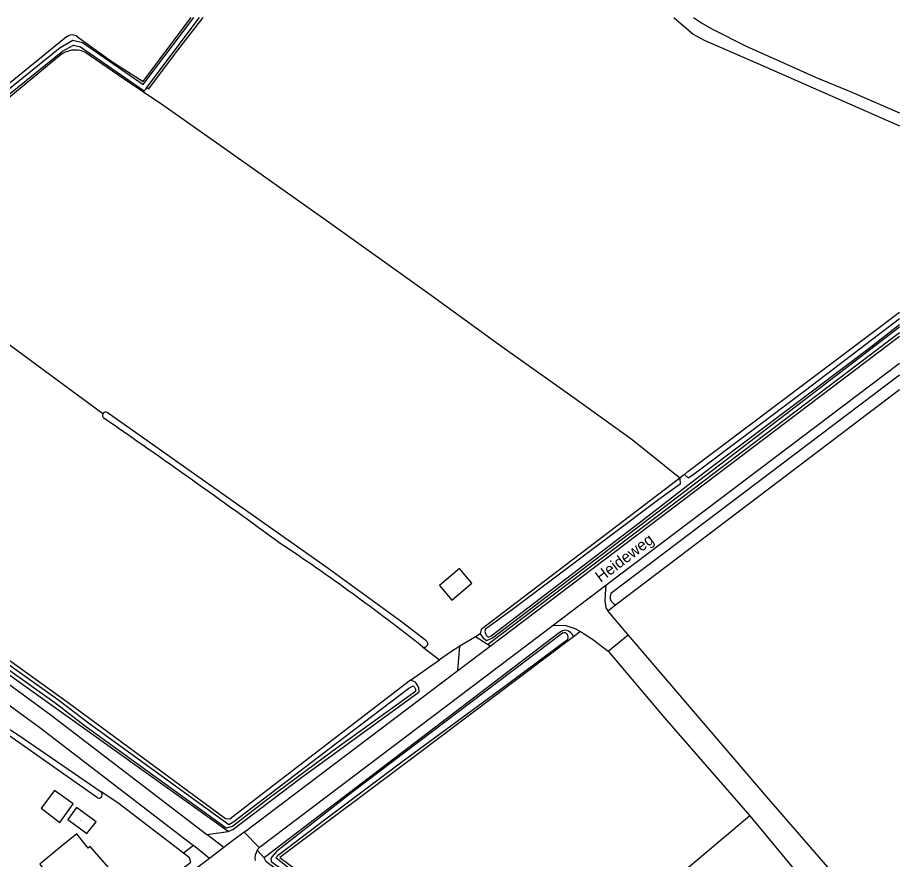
# Model space of a CAD drawing. Extents: x 141000 to 143000, y 400580 to 403500.
# Drawn here: x 142807.3 to 143000, y 403316 to 403500 of the extents above; entities that cross this region are included whole.
import ezdxf

# ---------------------------------------------------------------- set-up
doc = ezdxf.new("R2010")
doc.units = 0
for name, color, linetype in [('gg-afsc-muur', 7, 'Continuous'), ('gg-anno-openbare ruimte label', 7, 'Continuous'), ('gg-bbg-overig bouwwerk', 7, 'Continuous'), ('gg-knt-bronhoudergrens', 7, 'Continuous'), ('gg-knt-onverhard', 7, 'Continuous'), ('gg-knt-verharding', 7, 'Continuous'), ('gg-kntw-bovenkant insteek waterloop', 7, 'Continuous'), ('gg-kntw-waterlijn', 7, 'Continuous'), ('gt-grn-vlakafsluiter', 7, 'Continuous'), ('gt-grn-weggrens', 7, 'Continuous'), ('gx-grn-maaiveld', 7, 'Continuous'), ('kenmerkpunt-x pandkandidaat', 7, 'Continuous')]:
    doc.layers.add(name, color=color, linetype=linetype)

msp = doc.modelspace()

# ---------------------------------------------------------------- linework, layer by layer
at = {"layer": 'gg-afsc-muur'}
for points in [[(143000, 403257.58), (142974.61, 403289.01), (142983.17, 403296.46), (142992.55, 403304.89), (142971.44, 403329.16), (142940.76, 403365.11)], [(142967.32, 403325.5), (142947.35, 403308.65), (142956.55, 403298.23), (142927.33, 403272.64)]]:
    msp.add_lwpolyline(points, dxfattribs=at)
at = {"layer": 'gg-bbg-overig bouwwerk'}
for points in [[(142906.56, 403376.36), (142903.86, 403379.58), (142899.47, 403375.9), (142902.18, 403372.68), (142906.56, 403376.36)], [(142819.4, 403328.13), (142815.33, 403331.03), (142812.43, 403327.18), (142816.5, 403324.06), (142819.4, 403328.13)]]:
    msp.add_lwpolyline(points, dxfattribs=at)
at = {"layer": 'gg-knt-bronhoudergrens'}
for p, q in [((142825.88, 403413.4), (142772.65, 403452.66)), ((142893.17, 403355.15), (142899.51, 403359.63))]:
    msp.add_line(p, q, dxfattribs=at)
msp.add_lwpolyline([(142967.32, 403325.5), (142947.35, 403308.65), (142956.55, 403298.23), (142927.33, 403272.64)], dxfattribs=at)
at = {"layer": 'gg-knt-onverhard'}
msp.add_line((142895.76, 403362.49), (142899.51, 403359.63), dxfattribs=at)
at = {"layer": 'gg-knt-verharding'}
for p, q in [((142860.04, 403318.57), (142924.33, 403367.21)), ((142903.47, 403357.29), (142910.53, 403362.63)), ((142903.47, 403357.29), (142903.95, 403362.58)), ((142856.76, 403321.94), (142903.47, 403357.29)), ((142852.34, 403318.59), (142848.6, 403321.46)), ((142860.04, 403318.57), (142856.76, 403321.94)), ((142849.23, 403316.22), (142845.71, 403319.06))]:
    msp.add_line(p, q, dxfattribs=at)
for points in [[(142595.45, 403500), (142629.17, 403476.1), (142673.83, 403443.54), (142712.26, 403416.36), (142765.07, 403379.18), (142812.16, 403344.83), (142845.71, 403319.06)], [(142604.52, 403500), (142632.22, 403479.92), (142678.54, 403445.48), (142714.62, 403419.55), (142767.02, 403382.42), (142814.6, 403347.5), (142848.6, 403321.46)], [(142856.76, 403321.94), (142854.22, 403320.02), (142852.34, 403318.59)], [(142849.23, 403316.22), (142846.27, 403313.98), (142821.92, 403295.58)]]:
    msp.add_lwpolyline(points, dxfattribs=at)
for centre, radius, start, end in [((142862.86, 403316.16), 3.71, 150.6856, 185.8925), ((142862.83, 403316.19), 3.66, 139.4869, 150.8529)]:
    msp.add_arc(centre, radius, start, end, dxfattribs=at)
at = {"layer": 'gg-kntw-bovenkant insteek waterloop'}
msp.add_line((142824.75, 403329.45), (142800.19, 403346.65), dxfattribs=at)
for points in [[(142893.17, 403355.15), (142861.1, 403330.58), (142853.67, 403324.76), (142852.71, 403324.86), (142818.65, 403349.97), (142769.65, 403385.22), (142725.71, 403417.52)], [(142853.32, 403322.06), (142767.49, 403383.4), (142722.71, 403416.24)], [(142896.51, 403363.84), (142891.16, 403367.91), (142875.15, 403379.56), (142856.35, 403392.88), (142826.85, 403413.68)], [(142928.77, 403364.68), (142928.54, 403365.14), (142928.21, 403365.53), (142927.71, 403365.87), (142927.29, 403366.03), (142926.85, 403366.1), (142926.34, 403365.97), (142925.65, 403365.53), (142861.14, 403316.35)], [(142928.77, 403364.68), (142894.25, 403338.61), (142864.62, 403316.43), (142875.2, 403308.55), (142895.15, 403294.49), (142914.48, 403280.19)], [(142853.32, 403322.06), (142854.3, 403322.54), (142868.81, 403333.54), (142895.01, 403352.65), (142894.97, 403353.56), (142894.24, 403354.72), (142893.17, 403355.15)], [(142800.91, 403347.31), (142807.38, 403343.19), (142825.51, 403330.74)], [(142914.48, 403280.19), (142914.74, 403278.85), (142914.01, 403278.26), (142913.43, 403278.56), (142882.1, 403300.7), (142861.63, 403315.49), (142861.14, 403316.35)]]:
    msp.add_lwpolyline(points, dxfattribs=at)
for centre, radius, start, end in [((142826.51, 403413.05), 0.715, 151.044, 239.6172), ((142826.51, 403413.05), 0.715, 60.9592, 151.2266), ((141738.31, 401839.77), 1912.24, 53.91216, 55.32796), ((142604.25, 402993.89), 469.94, 51.6602, 56.3473), ((142896.16, 403363.15), 0.772, 305.4627, 63.0485), ((142896.16, 403363.15), 0.773, 239.1139, 305.3643), ((142825.05, 403330.13), 0.753, 245.7892, 53.1632)]:
    msp.add_arc(centre, radius, start, end, dxfattribs=at)
at = {"layer": 'gg-kntw-waterlijn'}
msp.add_line((142835.53, 403484.71), (142847.01, 403500), dxfattribs=at)
for points in [[(142780.76, 403376.1), (142810.98, 403354.58), (142816.01, 403351.02), (142822.75, 403345.86), (142853.42, 403323.63), (142854.52, 403324.27), (142876.78, 403341.25), (142892.79, 403353.4), (142893.72, 403353.93), (142894, 403353.63), (142894.21, 403353.21), (142894.23, 403352.73), (142876.35, 403339.82), (142861.95, 403329.13), (142854.21, 403323.18), (142852.84, 403322.82), (142822.15, 403345.06), (142815.41, 403350.21), (142810.4, 403353.77), (142780.18, 403375.29)], [(142926.37, 403365.48), (142909.35, 403352.56), (142880.64, 403330.85), (142863.85, 403317.73), (142862.92, 403316.61), (142862.64, 403316.21), (142862.67, 403315.57), (142870.65, 403309.82), (142891.9, 403294.45), (142913.15, 403279.4)], [(142913.15, 403279.4), (142913.57, 403279.37), (142913.86, 403279.61), (142913.84, 403280.14), (142910.8, 403282.15), (142871.59, 403310.16), (142864.44, 403315.75), (142863.75, 403316.34), (142864.27, 403317), (142874.63, 403324.86), (142891.52, 403337.54), (142913.77, 403353.88), (142925.24, 403362.38), (142927.45, 403364.06)]]:
    msp.add_lwpolyline(points, dxfattribs=at)
msp.add_arc((142926.69, 403364.6), 0.932, 324.4911, 110.0852, dxfattribs=at)
at = {"layer": 'gt-grn-vlakafsluiter'}
for p, q in [((142848.6, 403321.46), (142853.32, 403322.06)), ((142845.71, 403319.06), (142843.54, 403317.32)), ((142859.63, 403317.98), (142861.14, 403316.35))]:
    msp.add_line(p, q, dxfattribs=at)
for points in [[(142843.54, 403317.32), (142829.19, 403328.33), (142825.51, 403330.74)], [(142820.51, 403296.45), (142845.14, 403315.42), (142844.86, 403316.31), (142843.54, 403317.32)]]:
    msp.add_lwpolyline(points, dxfattribs=at)
at = {"layer": 'gt-grn-weggrens'}
msp.add_line((142852.34, 403318.59), (142849.23, 403316.22), dxfattribs=at)
at = {"layer": 'gx-grn-maaiveld'}
for p, q in [((142834.97, 403483.98), (142834.81, 403483.71)), ((142953.78, 403400.76), (143000, 403435.58)), ((142910.53, 403362.63), (143000, 403430.35)), ((142935.87, 403375.94), (143000, 403424.45)), ((142937.98, 403371.65), (143000, 403418.7)), ((142953.04, 403400.15), (142953.78, 403400.76)), ((142924.33, 403367.21), (142935.87, 403375.94)), ((142940.76, 403365.11), (142936.28, 403370.36)), ((142908.36, 403365.29), (142907.33, 403364.66)), ((142930.29, 403365.84), (142928.77, 403364.68)), ((142907.33, 403364.66), (142903.95, 403362.58)), ((142909.95, 403363), (142907.33, 403364.66)), ((142936.32, 403361.54), (142940.76, 403365.11)), ((142910.53, 403362.63), (142909.95, 403363)), ((142967.32, 403325.5), (142987.9, 403300.71))]:
    msp.add_line(p, q, dxfattribs=at)
for points in [[(142771.14, 403456.86), (142796.03, 403476.86), (142804.74, 403483.96), (142816.56, 403493.5), (142819.32, 403495.07), (142821.46, 403494.55), (142834.75, 403485.35), (142845.76, 403500)], [(142820.4, 403495.83), (142827.88, 403490.39), (142834.71, 403486.01), (142843.64, 403497.92), (142845.19, 403500)], [(142835.53, 403484.71), (142835.96, 403484.42), (142841.79, 403492.2), (142847.82, 403500)], [(142950.73, 403500), (142954.95, 403496.35), (142957.35, 403495.09), (142970.21, 403489.43), (143000, 403476.36)], [(142955.04, 403500), (142956.94, 403498.73), (142959.14, 403497.47), (142966.49, 403493.78), (142974.66, 403490.14), (142981.85, 403486.9), (142989.62, 403483.73), (143000, 403479.21)], [(142817.96, 403495.77), (142801.22, 403482.19), (142787.12, 403470.53), (142777.67, 403462.76), (142770.83, 403457.25)], [(142771.77, 403456.08), (142796.66, 403476.08), (142805.37, 403483.19), (142817.12, 403492.67), (142819.47, 403494), (142821.05, 403493.62), (142834.97, 403483.98)], [(142834.81, 403483.71), (142831.73, 403485.76), (142821.95, 403492.48)], [(142816.44, 403491.63), (142805.69, 403482.78), (142802.98, 403480.49), (142788.01, 403468.39), (142772.08, 403455.69)], [(142834.97, 403483.98), (142835.28, 403484.38), (142835.53, 403484.71)], [(142952.02, 403399.32), (142941.57, 403407.68), (142928.62, 403417.05), (142913.09, 403428.06), (142897.16, 403439.61), (142874.68, 403455.67), (142852.05, 403471.69), (142839.01, 403480.83), (142834.81, 403483.71)], [(142952.02, 403399.32), (142952.06, 403398.03), (142947.42, 403394.67), (142915.42, 403370.62), (142909.54, 403366.3), (142909.4, 403365.82), (142909.69, 403365.03), (142910.12, 403364.59), (142910.78, 403364.83), (142943.42, 403389.82), (142958.26, 403401.31), (142993.37, 403427.77), (143000, 403432.9)], [(142953.04, 403400.15), (142953.82, 403399.37), (142954.86, 403400.07), (142979.52, 403418.58), (143000, 403434.23)], [(142908.36, 403365.29), (142909.06, 403364.39), (142909.84, 403363.86), (142911.07, 403364.44), (142961.95, 403403.17), (143000, 403432.39)], [(142909.95, 403363), (142952.44, 403395.1), (143000, 403431.15)], [(143000, 403421.84), (142936.93, 403374.12), (142936.77, 403373.47), (142936.79, 403372.85), (142937.11, 403372.35), (142937.54, 403371.9), (142937.98, 403371.65)], [(142953.04, 403400.15), (142952.47, 403399.69), (142952.02, 403399.32)], [(142952.02, 403399.32), (142908.6, 403366.24), (142908.36, 403365.29)], [(142935.87, 403375.94), (142935.71, 403373.96), (142935.66, 403372.49), (142935.85, 403370.96), (142936.28, 403370.36)], [(142936.28, 403370.36), (142936.56, 403370.57), (142937.98, 403371.65)], [(142924.33, 403367.21), (142927.07, 403367.1), (142929.09, 403366.49), (142930.29, 403365.84)], [(142930.29, 403365.84), (142932.94, 403364.13), (142936.32, 403361.54)], [(142987.9, 403300.71), (142992.55, 403304.89), (142971.44, 403329.16), (142940.76, 403365.11)], [(142903.95, 403362.58), (142901.9, 403361.32), (142899.51, 403359.63)], [(142936.32, 403361.54), (142948.64, 403346.97), (142967.32, 403325.5)], [(142822.41, 403321.66), (142824.41, 403324.22), (142820.13, 403327.32), (142818.22, 403324.68), (142822.41, 403321.66)], [(142812.23, 403314.82), (142815, 403311.6), (142816.83, 403313.15), (142820.69, 403308.64), (142827.14, 403314.2), (142823.12, 403318.8), (142822.71, 403318.47), (142820.19, 403321.55), (142817.25, 403319.15), (142812.11, 403314.95), (142812.23, 403314.82)]]:
    msp.add_lwpolyline(points, dxfattribs=at)
for centre, radius, start, end in [((142819.22, 403494.21), 2, 54.0385, 128.9714), ((142819.86, 403487.76), 5.16, 66.104, 131.4618)]:
    msp.add_arc(centre, radius, start, end, dxfattribs=at)

# ---------------------------------------------------------------- texts
at = {"layer": 'gg-anno-openbare ruimte label'}
msp.add_text('Heideweg', height=2.5, rotation=37.1, dxfattribs=at).set_placement((142934.71, 403376.43))
at = {"layer": 'kenmerkpunt-x pandkandidaat'}
msp.add_text('PNDK', height=0.2, dxfattribs=at).set_placement((142820.94, 403324.36))

doc.saveas('drawing.dxf')
